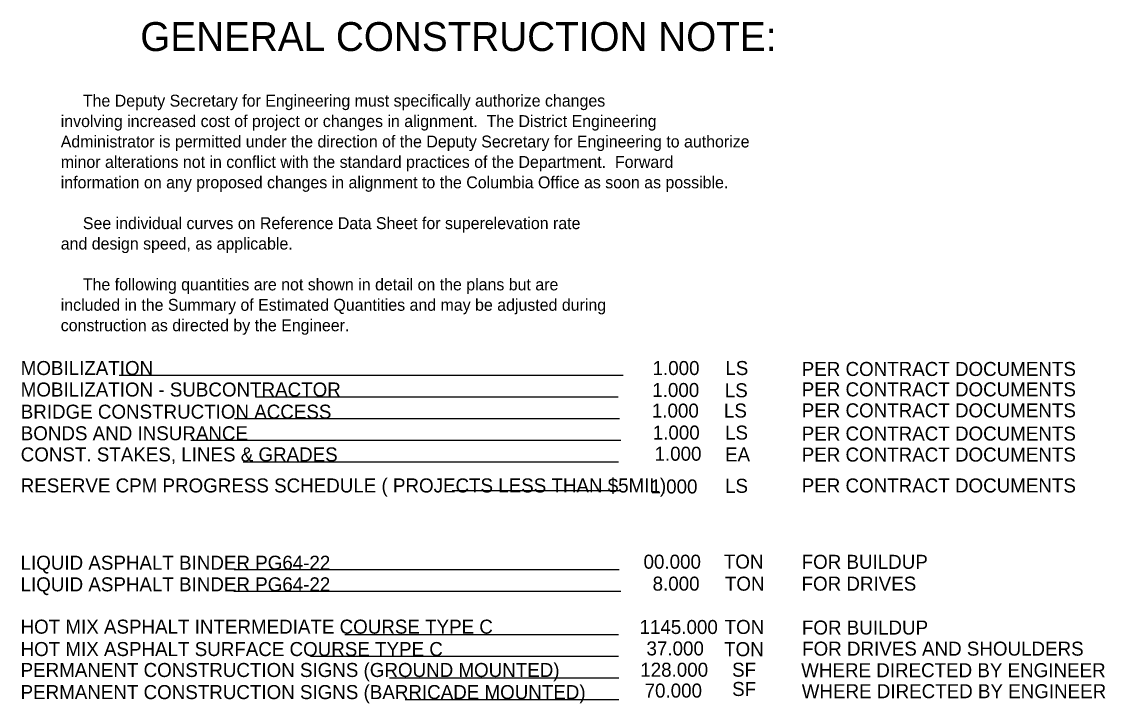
# Model space of a CAD drawing. Extents: x -13615 to 47191, y -1934 to 4415.
# Drawn here: x -11735 to -11116, y 1513 to 1902 of the extents above; entities that cross this region are included whole.
import ezdxf

# ---------------------------------------------------------------- set-up
doc = ezdxf.new("R2010")
doc.units = 0
doc.layers.add('Default', color=7, linetype='Continuous')

msp = doc.modelspace()

# ---------------------------------------------------------------- linework, layer by layer
at = {"layer": 'Default'}
for p, q in [((-11679.48, 1700.3), (-11427.92, 1700.3)), ((-11427.92, 1700.3), (-11415.73, 1700.3)), ((-11415.73, 1700.3), (-11412.03, 1700.3)), ((-11412.03, 1700.3), (-11409.44, 1700.3)), ((-11409.44, 1700.3), (-11400.46, 1700.3)), ((-11400.46, 1700.3), (-11394.44, 1700.3)), ((-11394.44, 1700.3), (-11391.48, 1700.3)), ((-11601.55, 1687.92), (-11427.94, 1687.92)), ((-11427.94, 1687.92), (-11416.12, 1687.92)), ((-11416.12, 1687.92), (-11411.34, 1687.92)), ((-11411.34, 1687.92), (-11409.21, 1687.92)), ((-11409.21, 1687.92), (-11400.33, 1687.92)), ((-11400.33, 1687.92), (-11394.37, 1687.92)), ((-11613.61, 1675.55), (-11427.95, 1675.55)), ((-11427.95, 1675.55), (-11416.5, 1675.55)), ((-11416.5, 1675.55), (-11410.64, 1675.55)), ((-11410.64, 1675.55), (-11408.97, 1675.55)), ((-11408.97, 1675.55), (-11400.21, 1675.55)), ((-11400.21, 1675.55), (-11394.29, 1675.55)), ((-11394.29, 1675.55), (-11393.65, 1675.55)), ((-11638.51, 1663.17), (-11427.97, 1663.17)), ((-11427.97, 1663.17), (-11416.88, 1663.17)), ((-11416.88, 1663.17), (-11409.94, 1663.17)), ((-11409.94, 1663.17), (-11408.74, 1663.17)), ((-11408.74, 1663.17), (-11400.08, 1663.17)), ((-11400.08, 1663.17), (-11394.22, 1663.17)), ((-11394.22, 1663.17), (-11392.78, 1663.17)), ((-11608.51, 1650.8), (-11427.99, 1650.8)), ((-11427.99, 1650.8), (-11417.27, 1650.8)), ((-11417.27, 1650.8), (-11408.5, 1650.8)), ((-11408.5, 1650.8), (-11399.95, 1650.8)), ((-11399.95, 1650.8), (-11394.14, 1650.8)), ((-11489.09, 1634.45), (-11393.19, 1634.45)), ((-11613.7, 1589.25), (-11428.04, 1589.25)), ((-11428.04, 1589.25), (-11416.58, 1589.25)), ((-11416.58, 1589.25), (-11410.72, 1589.25)), ((-11410.72, 1589.25), (-11409.05, 1589.25)), ((-11409.05, 1589.25), (-11400.29, 1589.25)), ((-11400.29, 1589.25), (-11394.37, 1589.25)), ((-11394.37, 1589.25), (-11393.73, 1589.25)), ((-11613.91, 1576.88), (-11428.05, 1576.88)), ((-11428.05, 1576.88), (-11416.97, 1576.88)), ((-11416.97, 1576.88), (-11410.03, 1576.88)), ((-11410.03, 1576.88), (-11408.82, 1576.88)), ((-11408.82, 1576.88), (-11400.16, 1576.88)), ((-11400.16, 1576.88), (-11394.3, 1576.88)), ((-11394.3, 1576.88), (-11392.87, 1576.88)), ((-11550.53, 1552.13), (-11428.09, 1552.13)), ((-11428.09, 1552.13), (-11417.73, 1552.13)), ((-11417.73, 1552.13), (-11408.35, 1552.13)), ((-11408.35, 1552.13), (-11399.91, 1552.13)), ((-11399.91, 1552.13), (-11394.15, 1552.13)), ((-11570.12, 1539.75), (-11428.11, 1539.75)), ((-11428.11, 1539.75), (-11418.11, 1539.75)), ((-11418.11, 1539.75), (-11408.12, 1539.75)), ((-11408.12, 1539.75), (-11399.78, 1539.75)), ((-11399.78, 1539.75), (-11394.08, 1539.75)), ((-11524.97, 1527.38), (-11428.12, 1527.38)), ((-11428.12, 1527.38), (-11418.5, 1527.38)), ((-11418.5, 1527.38), (-11407.88, 1527.38)), ((-11407.88, 1527.38), (-11399.65, 1527.38)), ((-11399.65, 1527.38), (-11394.01, 1527.38)), ((-11516.01, 1515), (-11428.14, 1515)), ((-11428.14, 1515), (-11418.88, 1515)), ((-11418.88, 1515), (-11407.65, 1515)), ((-11407.65, 1515), (-11399.53, 1515)), ((-11399.53, 1515), (-11393.93, 1515))]:
    msp.add_line(p, q, dxfattribs=at)

# ---------------------------------------------------------------- texts
for s, height, p in [('GENERAL CONSTRUCTION NOTE:', 16.524, (-11667.34, 1885.42)), ('     The Deputy Secretary for Engineering must specifically authorize changes', 6.804, (-11712.78, 1853.66)), ('involving increased cost of project or changes in alignment.  The District Engineering ', 6.804, (-11712.78, 1841.99)), ('Administrator is permitted under the direction of the Deputy Secretary for Engineering to authorize ', 6.804, (-11712.78, 1830.33)), ('minor alterations not in conflict with the standard practices of the Department.  Forward ', 6.804, (-11712.78, 1818.67)), ('information on any proposed changes in alignment to the Columbia Office as soon as possible.', 6.804, (-11712.78, 1807)), ('     See individual curves on Reference Data Sheet for superelevation rate', 6.804, (-11712.78, 1783.67)), ('and design speed, as applicable.', 6.804, (-11712.78, 1772.01)), ('     The following quantities are not shown in detail on the plans but are', 6.804, (-11712.78, 1748.68)), ('included in the Summary of Estimated Quantities and may be adjusted during', 6.804, (-11712.78, 1737.02)), ('construction as directed by the Engineer.', 6.804, (-11712.78, 1725.35)), ('MOBILIZATION', 8.0156, (-11735.64, 1700.31)), ('1.000', 8.016, (-11374.71, 1700.31)), ('LS', 8.016, (-11333.14, 1700.31)), ('PER CONTRACT DOCUMENTS', 8.0156, (-11289.5, 1699.78)), ('MOBILIZATION - SUBCONTRACTOR', 8.0156, (-11735.64, 1688.04)), ('PER CONTRACT DOCUMENTS', 8.0156, (-11289.5, 1688.14)), ('1.000', 8.016, (-11374.87, 1687.76)), ('LS', 8.016, (-11333.45, 1687.61)), ('1.000', 8.016, (-11375.1, 1675.98)), ('LS', 8.016, (-11333.93, 1676.01)), ('PER CONTRACT DOCUMENTS', 8.0156, (-11289.5, 1676.14)), ('BRIDGE CONSTRUCTION ACCESS', 8.0156, (-11735.64, 1675.38)), (' 1.000', 8.016, (-11377.58, 1663.44)), ('LS', 8.016, (-11333.3, 1663.43)), ('BONDS AND INSURANCE', 8.0156, (-11735.64, 1663.04)), ('PER CONTRACT DOCUMENTS', 8.0156, (-11289.5, 1662.87)), ('CONST. STAKES, LINES & GRADES', 8.0156, (-11735.64, 1650.96)), ('  1.000', 8.016, (-11379.55, 1651.36)), ('PER CONTRACT DOCUMENTS', 8.0156, (-11289.5, 1650.87)), ('EA', 8.016, (-11333.3, 1650.96)), ('RESERVE CPM PROGRESS SCHEDULE ( PROJECTS LESS THAN $5MIL)', 8.0156, (-11735.64, 1633.23)), ('1.000', 8.016, (-11375.88, 1632.66)), ('LS', 8.016, (-11333.3, 1633.02)), ('PER CONTRACT DOCUMENTS', 8.0156, (-11289.5, 1633.22)), ('LIQUID ASPHALT BINDER PG64-22', 8.0156, (-11735.72, 1589.09)), ('00.000', 8.016, (-11379.86, 1589.68)), ('TON', 8.016, (-11334.01, 1589.72)), ('FOR BUILDUP', 8.0156, (-11289.54, 1589.59)), ('LIQUID ASPHALT BINDER PG64-22', 8.0156, (-11735.72, 1576.74)), (' 8.000', 8.016, (-11377.66, 1577.14)), ('TON', 8.016, (-11333.38, 1577.13)), ('FOR DRIVES', 8.016, (-11289.59, 1577.14)), ('HOT MIX ASPHALT INTERMEDIATE COURSE TYPE C', 8.0156, (-11735.72, 1552.56)), (' 1145.000', 8.016, (-11385.12, 1552.37)), ('TON', 8.016, (-11333.54, 1552.41)), ('FOR BUILDUP', 8.0156, (-11289.38, 1552.06)), ('HOT MIX ASPHALT SURFACE COURSE TYPE C', 8.0156, (-11735.72, 1539.77)), (' 37.000', 8.016, (-11381.15, 1540.14)), ('TON', 8.016, (-11333.85, 1539.71)), ('FOR DRIVES AND SHOULDERS', 8.0156, (-11289.27, 1540)), ('PERMANENT CONSTRUCTION SIGNS (GROUND MOUNTED)', 8.0156, (-11735.72, 1527.81)), ('128.000', 8.016, (-11381.72, 1527.96)), ('SF', 8.016, (-11329.29, 1527.96)), ('WHERE DIRECTED BY ENGINEER', 8.0156, (-11289.8, 1527.68)), ('PERMANENT CONSTRUCTION SIGNS (BARRICADE MOUNTED)', 8.0156, (-11735.72, 1515.18)), ('70.000', 8.016, (-11379.25, 1516.05)), ('SF', 8.016, (-11329.25, 1516.96)), ('WHERE DIRECTED BY ENGINEER', 8.0156, (-11289.48, 1515.69))]:
    msp.add_text(s, height=height, dxfattribs=at).set_placement(p)

doc.saveas('drawing.dxf')
